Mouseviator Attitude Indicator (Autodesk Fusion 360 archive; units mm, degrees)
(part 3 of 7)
sketch "Sketch4" plane through (0, 2, 0) normal (0, -1, 0) x axis (1, 0, 0)
  line L1 (16.25, 38.3052) -> (16.25, 41.4655)
  line L2 (-16.25, -38.3052) -> (-16.25, -41.2776)
  line L3 (-16.25, -38.3052) -> (-16.25, -41.2776)
  line L4 (38.3052, -16.25) -> (41.2776, -16.25)
  line L5 (16.25, -41.2776) -> (16.25, -38.3052)
  line L6 (16.25, 41.4655) -> (24.1231, 41.4655)
  line L7 (41.2776, 16.25) -> (38.3052, 16.25)
  line L8 (41.2776, 29.1716) -> (41.2776, 16.25)
  line L9 (30.5858, 40.6918) -> (40.6918, 30.5858)
  line L10 (25.492, 41.2776) -> (29.1716, 41.2776)
  line L11 (41.2776, -16.25) -> (41.2776, -29.1716)
  line L12 (-41.2776, -29.1716) -> (-41.2776, -16.25)
  line L13 (-41.2776, -29.1716) -> (-41.2776, -16.25)
  line L14 (-41.2776, -16.25) -> (-38.3052, -16.25)
  line L15 (-30.5858, -40.6918) -> (-40.6918, -30.5858)
  line L16 (-16.25, -41.2776) -> (-29.1716, -41.2776)
  line L17 (29.1716, -41.2776) -> (16.25, -41.2776)
  line L18 (40.6918, -30.5858) -> (30.5858, -40.6918)
  line L19 (38.3052, -16.25) -> (41.2776, -16.25)
  line L20 (-41.2776, -16.25) -> (-38.3052, -16.25)
  line L21 (-30.5858, -40.6918) -> (-40.6918, -30.5858)
  line L22 (-16.25, -41.2776) -> (-29.1716, -41.2776)
  line L23 (16.25, -41.2776) -> (16.25, -38.3052)
  line L24 (29.1716, -41.2776) -> (16.25, -41.2776)
  line L25 (40.6918, -30.5858) -> (30.5858, -40.6918)
  line L26 (41.2776, -16.25) -> (41.2776, -29.1716)
  arc A1 centre (0, 0) radius 41.6095 clockwise from (-16.25, -38.3052) to (-17.58, -37.7133)
  arc A2 centre (0, 0) radius 41.6095 clockwise from (-16.25, -38.3052) to (-17.58, -37.7133)
  arc A3 centre (0, 0) radius 41.6095 clockwise from (17.58, -37.7133) to (16.25, -38.3052)
  circle C1 centre (-18.76, 36.96) radius 3.75
  circle C2 centre (-36.96, 18.76) radius 3.75
  circle C3 centre (-18.76, -36.96) radius 3.75
  circle C4 centre (18.76, -36.96) radius 3.75
  circle C5 centre (36.96, -18.76) radius 3.75
  circle C6 centre (36.96, 18.76) radius 3.75
  circle C7 centre (18.76, 36.96) radius 3.75
  circle C8 centre (-18.76, -36.96) radius 3.75
  circle C9 centre (-36.96, 18.76) radius 1.4
  circle C10 centre (-18.76, 36.96) radius 1.4
  circle C11 centre (18.76, 36.96) radius 1.4
  circle C12 centre (36.96, 18.76) radius 1.4
  circle C13 centre (36.96, -18.76) radius 1.4
  circle C14 centre (18.76, -36.96) radius 1.4
  circle C15 centre (-18.76, -36.96) radius 1.4
  circle C16 centre (-18.76, -36.96) radius 1.4
  arc A4 centre (0, 0) radius 41.6095 clockwise from (16.25, 38.3052) to (17.58, 37.7133)
  circle C17 centre (-36.96, -18.76) radius 3.75
  arc A5 centre (18.76, 36.96) radius 1.4 clockwise from (17.58, 37.7133) to (20.0646, 36.4522)
  arc A6 centre (0, 0) radius 41.6095 clockwise from (20.0646, 36.4522) to (36.4522, 20.0646)
  arc A7 centre (36.96, 18.76) radius 1.4 clockwise from (36.4522, 20.0646) to (37.7133, 17.58)
  arc A8 centre (0, 0) radius 41.6095 clockwise from (37.7133, 17.58) to (38.3052, 16.25)
  arc A9 centre (39.2776, 29.1716) radius 2 clockwise from (40.6918, 30.5858) to (41.2776, 29.1716)
  arc A10 centre (29.1716, 39.2776) radius 2 clockwise from (29.1716, 41.2776) to (30.5858, 40.6918)
  arc A11 centre (24.1231, 36.3855) radius 5.08 clockwise from (24.1231, 41.4655) to (25.492, 41.2776)
  circle C18 centre (31.4309, 31.4309) radius 2.159
  circle C19 centre (-36.96, -18.76) radius 1.4
  circle C20 centre (-31.4309, -31.4309) radius 2.159
  arc A12 centre (-39.2776, -29.1716) radius 2 clockwise from (-40.6918, -30.5858) to (-41.2776, -29.1716)
  arc A13 centre (-29.1716, -39.2776) radius 2 clockwise from (-29.1716, -41.2776) to (-30.5858, -40.6918)
  arc A14 centre (-18.76, -36.96) radius 1.4 clockwise from (-17.58, -37.7133) to (-20.0646, -36.4522)
  arc A15 centre (0, 0) radius 41.6095 clockwise from (-20.0646, -36.4522) to (-36.4522, -20.0646)
  arc A16 centre (-36.96, -18.76) radius 1.4 clockwise from (-36.4522, -20.0646) to (-37.7133, -17.58)
  arc A17 centre (0, 0) radius 41.6095 clockwise from (-37.7133, -17.58) to (-38.3052, -16.25)
  circle C21 centre (31.4309, -31.4309) radius 2.159
  arc A18 centre (0, 0) radius 41.6095 clockwise from (17.58, -37.7133) to (16.25, -38.3052)
  arc A19 centre (29.1716, -39.2776) radius 2 clockwise from (30.5858, -40.6918) to (29.1716, -41.2776)
  arc A20 centre (39.2776, -29.1716) radius 2 clockwise from (41.2776, -29.1716) to (40.6918, -30.5858)
  arc A21 centre (0, 0) radius 41.6095 clockwise from (38.3052, -16.25) to (37.7133, -17.58)
  arc A22 centre (36.96, -18.76) radius 1.4 clockwise from (37.7133, -17.58) to (36.4522, -20.0646)
  arc A23 centre (0, 0) radius 41.6095 clockwise from (36.4522, -20.0646) to (20.0646, -36.4522)
  arc A24 centre (18.76, -36.96) radius 1.4 clockwise from (20.0646, -36.4522) to (17.58, -37.7133)
  circle C22 centre (-31.4309, -31.4309) radius 2.159
  arc A25 centre (-39.2776, -29.1716) radius 2 clockwise from (-40.6918, -30.5858) to (-41.2776, -29.1716)
  arc A26 centre (-29.1716, -39.2776) radius 2 clockwise from (-29.1716, -41.2776) to (-30.5858, -40.6918)
  arc A27 centre (-18.76, -36.96) radius 1.4 clockwise from (-17.58, -37.7133) to (-20.0646, -36.4522)
  arc A28 centre (0, 0) radius 41.6095 clockwise from (-20.0646, -36.4522) to (-36.4522, -20.0646)
  arc A29 centre (-36.96, -18.76) radius 1.4 clockwise from (-36.4522, -20.0646) to (-37.7133, -17.58)
  arc A30 centre (0, 0) radius 41.6095 clockwise from (-37.7133, -17.58) to (-38.3052, -16.25)
  circle C23 centre (31.4309, -31.4309) radius 2.159
  arc A31 centre (29.1716, -39.2776) radius 2
  arc A32 centre (39.2776, -29.1716) radius 2 clockwise from (41.2776, -29.1716) to (40.6918, -30.5858)
  arc A33 centre (0, 0) radius 41.6095 clockwise from (38.3052, -16.25) to (37.7133, -17.58)
  arc A34 centre (36.96, -18.76) radius 1.4 clockwise from (37.7133, -17.58) to (36.4522, -20.0646)
  arc A35 centre (0, 0) radius 41.6095 clockwise from (36.4522, -20.0646) to (20.0646, -36.4522)
  arc A36 centre (18.76, -36.96) radius 1.4 clockwise from (20.0646, -36.4522) to (17.58, -37.7133)
  arc A37 centre (-36.96, -18.76) radius 1.4 clockwise from (-37.7133, -17.58) to (-36.4522, -20.0646)
  concentric C1 C10
  concentric C2 C9
  concentric C3 C15
  concentric C4 C14
  concentric C5 C13
  concentric C6 C12
  concentric C7 C11
  concentric C8 C16
  equal C3 C8
  equal C2 C3
  equal C1 C2
  equal C1 C7
  equal C6 C7
  equal C5 C6
  equal C4 C5
  equal C3 C17
  concentric C17 C19
  dimension "d321" diameter C5 = 7.5
extrude "Extrude4" add sketch "Sketch4" profile of L1 A1 L2 A2 A3 C9 C10 C11 C12 C13 C14 C1 C2 C15 C3 C4 C5 C6 C7 C16 C8 L3 L4 A4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 against normal blind 5
sketch "Sketch2" plane through (0, 1, 0) normal (0, 1, 0) x axis (-1, 0, 0)
  line L1 (-1.35, -41.3) -> (-1.35, -39.627)
  line L2 (1.35, -41.3) -> (-1.35, -41.3)
  line L3 (1.35, -39.627) -> (1.35, -41.3)
  line L4 (9.5326, -23.75) -> (27.9134, -23.75)
  line L5 (3.7293, -12.6019) -> (9.5326, -23.75)
  line L6 (-3.7293, -12.6019) -> (3.7293, -12.6019)
  line L7 (-9.5326, -23.75) -> (-3.7293, -12.6019)
  line L8 (-27.9134, -23.75) -> (-9.5326, -23.75)
  line L9 (-3.543, 32.597) -> (-3.543, 36.4783)
  line L10 (-2.0322, 27.1385) -> (-3.543, 32.597)
  line L11 (-0.9183, 27.1385) -> (-2.0322, 27.1385)
  line L12 (-0.9183, 36.6385) -> (-0.9183, 27.1385)
  line L13 (0.9183, 27.1385) -> (0.9183, 36.6385)
  line L14 (2.0322, 27.1385) -> (0.9183, 27.1385)
  line L15 (3.543, 32.597) -> (2.0322, 27.1385)
  line L16 (3.543, 36.4783) -> (3.543, 32.597)
  line L17 (-31.75, -23.75) -> (31.75, -23.75)
  line L18 (-40.6918, 30.5858) -> (-30.5858, 40.6918)
  line L19 (-41.2776, -29.1716) -> (-41.2776, 29.1716)
  line L20 (-30.5858, -40.6918) -> (-40.6918, -30.5858)
  line L21 (-1.5, -41.2776) -> (-29.1716, -41.2776)
  line L22 (-1.5, -39.6216) -> (-1.5, -41.2776)
  line L23 (1.5, -41.2776) -> (1.5, -39.6216)
  line L24 (29.1716, -41.2776) -> (1.5, -41.2776)
  line L25 (40.6918, -30.5858) -> (30.5858, -40.6918)
  line L26 (41.2776, 29.1716) -> (41.2776, -29.1716)
  line L27 (30.5858, 40.6918) -> (40.6918, 30.5858)
  line L28 (25.502, 41.2776) -> (29.1716, 41.2776)
  line L29 (-24.1231, 41.4655) -> (24.1331, 41.4655)
  line L30 (-29.1716, 41.2776) -> (-25.492, 41.2776)
  arc A1 centre (0, 0) radius 39.65 clockwise from (-1.35, -39.627) to (1.35, -39.627)
  arc A2 centre (0, 0) radius 36.65 clockwise from (-27.9134, -23.75) to (-3.543, 36.4783)
  arc A3 centre (0, 0) radius 36.65 clockwise from (-0.9183, 36.6385) to (0.9183, 36.6385)
  arc A4 centre (0, 0) radius 36.65 clockwise from (3.543, 36.4783) to (27.9134, -23.75)
  arc A5 centre (-39.2776, 29.1716) radius 2 clockwise from (-41.2776, 29.1716) to (-40.6918, 30.5858)
  arc A6 centre (-39.2776, -29.1716) radius 2 clockwise from (-40.6918, -30.5858) to (-41.2776, -29.1716)
  arc A7 centre (-29.1716, -39.2776) radius 2 clockwise from (-29.1716, -41.2776) to (-30.5858, -40.6918)
  arc A8 centre (0, 0) radius 39.65 clockwise from (-1.5, -39.6216) to (1.5, -39.6216)
  arc A9 centre (29.1716, -39.2776) radius 2 clockwise from (30.5858, -40.6918) to (29.1716, -41.2776)
  arc A10 centre (39.2776, -29.1716) radius 2 clockwise from (41.2776, -29.1716) to (40.6918, -30.5858)
  arc A11 centre (39.2776, 29.1716) radius 2 clockwise from (40.6918, 30.5858) to (41.2776, 29.1716)
  arc A12 centre (29.1716, 39.2776) radius 2 clockwise from (29.1716, 41.2776) to (30.5858, 40.6918)
  arc A13 centre (24.1331, 36.3855) radius 5.08 clockwise from (24.1331, 41.4655) to (25.502, 41.2776)
  arc A14 centre (-24.1231, 36.3855) radius 5.08 clockwise from (-25.492, 41.2776) to (-24.1231, 41.4655)
  arc A15 centre (-29.1716, 39.2776) radius 2 clockwise from (-30.5858, 40.6918) to (-29.1716, 41.2776)
  circle C1 centre (-36.96, 18.76) radius 1.4
  circle C2 centre (-18.76, -36.96) radius 1.4
  circle C3 centre (36.96, -18.76) radius 1.4
  circle C4 centre (18.76, 36.96) radius 1.4
  circle C5 centre (36.96, 18.76) radius 1.4
  circle C6 centre (18.76, -36.96) radius 1.4
  circle C7 centre (-36.96, -18.76) radius 1.4
  circle C8 centre (-18.76, 36.96) radius 1.4
  circle C9 centre (-31.4309, 31.4309) radius 2.159
  circle C10 centre (-31.4309, -31.4309) radius 2.159
  circle C11 centre (31.4309, 31.4309) radius 2.159
  circle C12 centre (31.4309, -31.4309) radius 2.159
  point P23 (31.75, -23.75)
  point P24 (-31.75, -23.75)
  point P12 (-27.9134, -23.75)
  coincident A1 P23
  coincident A1 P24
  parallel L4 L17
  horizontal P12 P24
extrude "Extrude3" add sketch "Sketch2" profile of A1 A2 L9 L10 L11 L12 A3 L13 L14 L15 L16 A4 L17 A8 against normal blind 2.5
work_plane "WorkPlane1" AlongDistance -1.5
sketch "Sketch5" plane through (0, 0, 11.5) normal (0, 0, 1) x axis (1, 0, 0)
  line L1 (0, 5.902) -> (-0.4092, 6.2366)
  line L2 (0, 8.6817) -> (0, 0)
  line L3 (0, 5.902) -> (0.4092, 6.2366)
  circle C1 centre (0, 0) radius 6.25
  point P1 (0, 0)
  point P4 (0, 0)
  point P3 (0, 5.902)
  point P2 (-0.4092, 6.2366)
  point P7 (0.4092, 6.2366)
  point P8 (0, 5.902)
  coincident P1 P4
  vertical L2
  coincident P3 L2
  coincident P2 C1
  symmetric P2 L2 P7
  symmetric P3 L2 P8
extrude "Extrude5" cut sketch "Sketch5" profile of L1 C1 L3 along a picked direction blind -5
circular_pattern "C-Pattern1" countU 30 TotalAngle 360
extrude "Extrude5" cut sketch "Lil Microswitch zero nub" profile of C3 C4 to an object
extrude "Extrude5" cut of existing geometry to an object
sketch "Sketch3" plane through (0, 0, 39.7655) normal (0, 0, 1) x axis (-1, 0, 0)
  line L1 (15.15, 6.4) -> (22.19, 6.4)
  line L2 (15.15, 0.15) -> (15.15, 6.4)
  line L3 (5.6554, 0.15) -> (15.15, 0.15)
  line L4 (-15.15, 0.15) -> (-5.6554, 0.15)
  line L5 (-15.15, 6.4) -> (-15.15, 0.15)
  line L6 (-22.19, 6.4) -> (-15.15, 6.4)
  line L7 (-4.7586, 0.1) -> (-22.19, 0.1)
  line L8 (15.15, 0.1) -> (15.15, 0.15)
  line L9 (-15.15, 0.1) -> (-15.15, 0.15)
  line L10 (15.15, 3.275) -> (-15.15, 3.275)
  line L11 (15.15, 0.1) -> (15.15, 3.275)
  line L12 (-15.15, 0.1) -> (15.15, 0.1)
  line L13 (-15.15, 3.275) -> (-15.15, 0.1)
  line L14 (22.19, 0.1) -> (4.7586, 0.1)
  arc A1 centre (-22.19, 3.3) radius 1.6 clockwise from (-20.5902, 3.275) to (-23.7898, 3.275)
  arc A2 centre (-22.19, 3.25) radius 1.6 clockwise from (-23.7898, 3.275) to (-20.5902, 3.275)
  closed curve K1 centre (2.5644, 3.3)
  closed curve K2 centre (-2.5644, 3.3)
  arc A3 centre (-22.19, 3.25) radius 3.15 clockwise from (-22.19, 0.1) to (-22.19, 6.4)
  arc A4 centre (22.19, 3.25) radius 3.15 clockwise from (22.19, 6.4) to (22.19, 0.1)
  arc A5 centre (22.19, 3.25) radius 1.6 clockwise from (20.5902, 3.275) to (23.7898, 3.275)
  arc A6 centre (22.19, 3.3) radius 1.6 clockwise from (23.7898, 3.275) to (20.5902, 3.275)
  circle C1 centre (22.19, 3.25) radius 1.6
  circle C2 centre (-22.19, 3.25) radius 1.6
  point P8 (15.15, 0.15)
  point P25 (15.15, 0.15)
  point P26 (15.15, 0.1)
  point P14 (-15.15, 0.15)
  point P27 (-15.15, 0.15)
  point P29 (-15.15, 3.275)
  coincident P8 P25
  coincident L7 P26
  perpendicular L7 L8
  coincident P14 P27
  perpendicular L7 L9
  horizontal L10
  vertical L11
  horizontal L12
  vertical L13
  midpoint L5 P29
extrude "Extrude6" cut sketch "Sketch3" profile of A1 A6 C1 C2 to an object
extrude "Extrude7" cut sketch "Sketch3" profile of L2 L3 K1 K2 L4 L5 L7 L8 L9 L10 L11 L12 L13 to an object
chamfer "Chamfer1" distance 1
sketch "Sketch1" plane through (26, 0, 0) normal (1, 0, 0) x axis (0, 1, 0)
  line L1 (25.28, 27) -> (57.28, 27)
  line L2 (25.28, 19) -> (25.28, 27)
  line L3 (17.9124, 19) -> (25.28, 19)
  line L4 (25.28, -19) -> (17.9124, -19)
  line L5 (25.28, -27) -> (25.28, -19)
  line L6 (57.28, -27) -> (25.28, -27)
  line L7 (57.28, 27) -> (57.28, -27)
  circle C1 centre (44.28, 0) radius 5
  arc A1 centre (44.28, 0) radius 32.5 clockwise from (14.7028, 13.47) to (17.9124, 19)
  arc A2 centre (44.28, 0) radius 32.5 clockwise from (14.7028, -13.47) to (14.7028, 13.47)
  circle C2 centre (36.955, 17.5) radius 2
  circle C3 centre (36.955, -17.5) radius 2
  circle C4 centre (30.1171, 16.6312) radius 1.6
  circle C5 centre (30.1171, -16.6312) radius 1.6
  arc A3 centre (44.28, 0) radius 32.5 clockwise from (17.9124, -19) to (14.7028, -13.47)
hole "Hole2" HoleDepth 12 HoleDiameter 3.6 TipAngle 180 CSDiameter 6.3 CSAngle 90
extrude "Extrude7" add sketch "Right Arm" profile of L1 L3 L4 C1 L9 A4 L10 A3 to an object
fillet "Fillet1" radius 1 4 1.5
sketch "Sketch7" plane through (30.62, 0, 0) normal (-1, 0, 0) x axis (0, -1, 0)
  line L1 (-44.28, 3.75) -> (-9.9844, 3.75)
  line L2 (-9.9844, -3.75) -> (-44.28, -3.75)
  line L3 (-39.28, -3.75) -> (-24.28, -3.75)
  line L4 (-39.28, 3.75) -> (-39.28, -3.75)
  line L5 (-24.28, 3.75) -> (-39.28, 3.75)
  line L6 (-24.28, -3.75) -> (-24.28, 3.75)
  line L7 (-49.28, -2.25) -> (-49.28, 2.25)
  arc A1 centre (-44.28, 0) radius 34.5 clockwise from (-9.9844, 3.75) to (-9.9844, -3.75)
  arc A2 centre (-44.28, 0) radius 3.75 clockwise from (-44.28, 3.75) to (-44.28, -3.75)
  point P9 (-39.28, 3.75)
  point P7 (-24.28, -3.75)
  point P10 (-24.28, 3.75)
  horizontal L3
  vertical L4
  horizontal L5
  vertical L6
  coincident L1 P9
  coincident L2 P7
  dimension "d393" distance P9 P10 = 15
  dimension "d394" distance P9 L7 = 10
extrude "Extrude8" add sketch "Sketch7" profile of L1 L2 L3 L4 L5 L6 along normal blind 3
external_derived "Analog Master"
sketch "Attitude Hole Trace" plane through (0, 0, 0) normal (0, 1, 0) x axis (1, 0, 0)
  line L1 (-264.7779, -374.3404) -> (-260.0107, -379.2613)
  line L2 (-257.8455, -377.1638) -> (-262.6127, -372.2429)
  line L3 (-197.0382, -372.2859) -> (-201.9591, -377.0531)
  line L4 (-199.8616, -379.2183) -> (-194.9407, -374.4511)
  line L5 (-259.8999, -309.4241) -> (-264.8209, -314.1913)
  line L6 (-262.7234, -316.3565) -> (-257.8025, -311.5893)
  line L7 (-194.9837, -314.302) -> (-199.7509, -309.3811)
  line L8 (-201.9161, -311.4786) -> (-197.1489, -316.3995)
  arc A1 centre (-263.6953, -373.2916) radius 1.5073 clockwise from (-264.7779, -374.3404) to (-262.6127, -372.2429)
  arc A2 centre (-258.9281, -378.2126) radius 1.5073 clockwise from (-257.8455, -377.1638) to (-260.0107, -379.2613)
  circle C1 centre (-229.8808, -344.3212) radius 40.005
  arc A3 centre (-195.9894, -373.3685) radius 1.5073 clockwise from (-197.0382, -372.2859) to (-194.9407, -374.4511)
  arc A4 centre (-200.9104, -378.1357) radius 1.5073 clockwise from (-199.8616, -379.2183) to (-201.9591, -377.0531)
  arc A5 centre (-258.8512, -310.5067) radius 1.5073 clockwise from (-259.8999, -309.4241) to (-257.8025, -311.5893)
  arc A6 centre (-263.7722, -315.2739) radius 1.5073 clockwise from (-262.7234, -316.3565) to (-264.8209, -314.1913)
  arc A7 centre (-196.0663, -315.3508) radius 1.5073 clockwise from (-194.9837, -314.302) to (-197.1489, -316.3995)
  arc A8 centre (-200.8335, -310.4298) radius 1.5073 clockwise from (-201.9161, -311.4786) to (-199.7509, -309.3811)
chamfer "Chamfer1" distance 8
chamfer "Chamfer2" distance 6 distance 8
decal "Decal1"
sketch "Sketch7" plane through (0, 57.28, 0) normal (0, -1, 0) x axis (1, 0, 0)
  line L1 (-26, -14.5) -> (-23, -14.5)
  line L2 (-26, -27) -> (-26, -14.5)
  line L3 (23, -27) -> (-26, -27)
  line L4 (23, 27) -> (23, -27)
  line L5 (-26, 27) -> (23, 27)
  line L6 (-26, 14.5) -> (-26, 27)
  line L7 (-23, 14.5) -> (-26, 14.5)
  line L8 (-23, -14.5) -> (-23, 14.5)
  line L9 (-1.7896, -1.76) -> (1.7896, -1.76)
  line L10 (1.7896, 1.76) -> (-1.7896, 1.76)
  line L11 (-13.75, 8.75) -> (-21.25, 8.75)
  line L12 (-13.75, -8.75) -> (-13.75, 8.75)
  line L13 (-21.25, -8.75) -> (-13.75, -8.75)
  line L14 (-21.25, 8.75) -> (-21.25, -8.75)
  line L15 (-21.25, 8.75) -> (-13.75, 8.75)
  line L16 (-21.25, -8.75) -> (-21.25, 8.75)
  line L17 (-13.75, -8.75) -> (-21.25, -8.75)
  line L18 (-13.75, 8.75) -> (-13.75, -8.75)
  line L19 (26, -27) -> (26, 27)
  line L20 (-26, -27) -> (26, -27)
  line L21 (-26, 27) -> (-26, -27)
  line L22 (-17.1756, 27) -> (-26, 27)
  line L23 (-18.009, 31.2447) -> (-2.1571, 29.8579)
  line L24 (-19.3529, 15.8845) -> (-18.009, 31.2447)
  line L25 (-3.5009, 14.4976) -> (-19.3529, 15.8845)
  line L26 (-2.1571, 29.8579) -> (-3.5009, 14.4976)
  line L27 (-4, 25) -> (-13.4638, 25.828)
  line L28 (26, 27) -> (17.1756, 27)
  line L29 (-2.75, 27.25) -> (-2.75, 31.8816)
  line L30 (2.75, 27.25) -> (-2.75, 27.25)
  line L31 (2.75, 31.8816) -> (2.75, 27.25)
  circle C1 centre (0, -23) radius 2.75
  circle C2 centre (0, 23) radius 2.75
  arc A1 centre (0, 0) radius 2.51 clockwise from (1.7896, 1.76) to (1.7896, -1.76)
  arc A2 centre (0, 0) radius 2.51 clockwise from (-1.7896, -1.76) to (-1.7896, 1.76)
  circle C3 centre (-13.4638, 25.828) radius 1.2
  circle C4 centre (-4, 25) radius 1.2
  circle C5 centre (0, -23) radius 2.75
  circle C6 centre (0, 23) radius 2.75
  circle C7 centre (0, 0) radius 6.25
  arc A3 centre (0, 0) radius 32 clockwise from (2.75, 31.8816) to (17.1756, 27)
  arc A4 centre (0, 0) radius 32 clockwise from (-17.1756, 27) to (-2.75, 31.8816)
  point P21 (-13.4638, 25.828)
  point P38 (-13.4638, 25.828)
  point P22 (-4, 25)
  point P39 (-4, 25)
  perpendicular L23 L24
  parallel L23 L25
  parallel L24 L26
  coincident P21 P38
  coincident P22 P39
  parallel L25 L27
  dimension "d416" distance L23 L27 = 5
  dimension "d417" distance L24 P38 = 5
work_plane "WorkPlane2" AlongDistance -57
sketch "Sketch5" plane through (0, 7, 0.094) normal (0, 1, 0) x axis (1, 0, 0)
  line L1 (-26.6906, -32.6071) -> (-30.1607, -36.0772)
  line L2 (-27.9608, -27.8668) -> (-26.6906, -32.6071)
  line L3 (-32.701, -26.5967) -> (-27.9608, -27.8668)
  line L4 (-36.1712, -30.0668) -> (-32.701, -26.5967)
  line L5 (-34.901, -34.807) -> (-36.1712, -30.0668)
  line L6 (-30.1607, -36.0772) -> (-34.901, -34.807)
  line L7 (-35.2553, -22.1941) -> (-22.1001, -35.3492)
  line L8 (30.0668, -36.1712) -> (26.5967, -32.701)
  line L9 (34.807, -34.901) -> (30.0668, -36.1712)
  line L10 (36.0772, -30.1607) -> (34.807, -34.901)
  line L11 (32.6071, -26.6906) -> (36.0772, -30.1607)
  line L12 (36.1712, 30.0668) -> (32.701, 26.5967)
  line L13 (34.901, 34.807) -> (36.1712, 30.0668)
  line L14 (30.1607, 36.0772) -> (34.901, 34.807)
  line L15 (26.6906, 32.6071) -> (30.1607, 36.0772)
  line L16 (-30.0668, 36.1712) -> (-26.5967, 32.701)
  line L17 (-34.807, 34.901) -> (-30.0668, 36.1712)
  line L18 (-36.0772, 30.1607) -> (-34.807, 34.901)
  line L19 (-32.6071, 26.6906) -> (-36.0772, 30.1607)
  line L20 (-25.7665, -31.6829) -> (-26.6906, -32.6071)
  line L21 (-31.7769, -25.6725) -> (-32.701, -26.5967)
  line L22 (25.6725, -31.7769) -> (26.5967, -32.701)
  line L23 (31.6829, -25.7665) -> (32.6071, -26.6906)
  line L24 (22.1941, -35.2553) -> (35.3492, -22.1001)
  line L25 (31.7769, 25.6725) -> (32.701, 26.5967)
  line L26 (25.7665, 31.6829) -> (26.6906, 32.6071)
  line L27 (35.2553, 22.1941) -> (22.1001, 35.3492)
  line L28 (-25.6725, 31.7769) -> (-26.5967, 32.701)
  line L29 (-31.6829, 25.7665) -> (-32.6071, 26.6906)
  line L30 (-22.1941, 35.2553) -> (-35.3492, 22.1001)
  circle C1 centre (31.4309, -31.3369) radius 2.159
  circle C2 centre (-31.4309, 31.5249) radius 2.159
  circle C3 centre (31.4309, 31.5249) radius 2.159
  circle C4 centre (-31.4309, -31.3369) radius 2.159
  arc A1 centre (0, 0.094) radius 41.6095 clockwise from (-22.1001, -35.1613) to (-35.2553, -22.0062)
  point P11 (-31.4309, -31.3369)
  point P43 (-31.4309, -31.3369)
  point P29 (-25.7665, -31.6829)
  point P30 (-31.7769, -25.6725)
  coincident P11 P43
  perpendicular L1 L7
  coincident L7 P29
  perpendicular L7 L20
  coincident L7 P30
  perpendicular L7 L21
  dimension "d404" distance P11 L6 = 4.25
  dimension "d408" C-Pattern1-Angle = 360
extrude "Extrude6" cut sketch "Sketch5" profile of C1 C4 C2 C3 L1 L2 L3 L4 L5 L6 L8 L9 L10 L11 L12 L13 L14 L15 L16 L17 L18 L19 along normal blind 4
component_insert "Component Insert7"
joint "Assemble9" alignAngle 0 alignOffsetX 0 alignOffsetY 0 alignOffsetZ 1
sketch "Sketch8" plane through (-34.12, 0, 0) normal (-1, 0, 0) x axis (0, -1, 0)
  line L1 (-7.28, -4) -> (-47.78, -4)
  line L2 (-7.28, 4) -> (-7.28, -4)
  line L3 (-47.78, 4) -> (-7.28, 4)
  line L4 (-49.28, -2.5) -> (-49.28, 2.5)
  line L5 (-24.905, -2.625) -> (-19.655, -2.625)
  line L6 (-24.905, 2.625) -> (-24.905, -2.625)
  line L7 (-19.655, 2.625) -> (-24.905, 2.625)
  line L8 (-19.655, -2.625) -> (-19.655, 2.625)
  line L9 (-24.905, 2.625) -> (-19.655, -2.625)
  line L10 (-19.655, 2.625) -> (-24.905, -2.625)
  line L11 (-26.405, 4.125) -> (-18.155, 4.125)
  line L12 (-26.405, -4.125) -> (-26.405, 4.125)
  line L13 (-18.155, -4.125) -> (-26.405, -4.125)
  line L14 (-18.155, 4.125) -> (-18.155, -4.125)
  line L15 (-26.405, -4.125) -> (-18.155, 4.125)
  line L16 (-18.155, -4.125) -> (-26.405, 4.125)
  arc A1 centre (-47.78, -2.5) radius 1.5 clockwise from (-47.78, -4) to (-49.28, -2.5)
  arc A2 centre (-47.78, 2.5) radius 1.5 clockwise from (-49.28, 2.5) to (-47.78, 4)
  circle C1 centre (-44.28, 0) radius 1.5
  point P15 (-22.28, 0)
  point P1 (0, 0)
  point P20 (-22.28, 0)
  point P13 (-24.905, 2.625)
  point P14 (-19.655, 2.625)
  point P12 (-24.905, -2.625)
  point P10 (-44.28, 0)
  horizontal L5
  perpendicular L5 L6
  parallel L5 L7
  parallel L6 L8
  coincident L9 P15
  coincident L10 P15
  horizontal P1 P15
  horizontal L11
  perpendicular L11 L12
  parallel L11 L13
  parallel L12 L14
  coincident L15 P20
  coincident L16 P20
  coincident P15 P20
  dimension "d452" distance P13 P14 = 5.25
  dimension "d453" distance P12 P13 = 5.25
  dimension "d454" distance P10 P15 = 22 (= "MagPitchDim")
  dimension "d456" distance L8 L14 = 1.5
  dimension "d457" distance L7 L11 = 1.5
extrude "Extrude9" add sketch "Sketch8" profile of L1 L3 L5 L6 L7 L8 L12 L14 along normal blind 2.5
extrude "Extrude10" cut of existing geometry blind -2.5
extrude "Extrude11" sketch "Sketch8" profile of L1 L3 L5 L6 L7 L8 L12 L14 blind 1
hole "Hole1" HoleDepth 1 HoleDiameter 2 TipAngle 180
decal "Decal1"
base_feature "Base Feature"
joint "Assemble8" alignAngle -15 alignOffsetX 0 alignOffsetY 0 alignOffsetZ 0
step "C-Pattern" TotalAngle 360
extrude "Extrude12" add sketch "Sketch7" profile of L5 C3 L22 L23 L24 L26 to an object
hole "Hole3" HoleDepth 7 HoleDiameter 2 TipAngle 180 CSDiameter 3 CSAngle 90
sketch "Pitch Hall'" plane through (-23, 0, 0) normal (1, 0, 0) x axis (0, 1, 0)
  line L1 (55.28, -14.5) -> (15.1939, -14.5)
  line L2 (15.1939, 14.5) -> (55.28, 14.5)
  line L3 (19.28, -2.35) -> (25.28, -2.35)
  line L4 (19.28, 2.35) -> (19.28, -2.35)
  line L5 (25.28, 2.35) -> (19.28, 2.35)
  line L6 (25.28, -2.35) -> (25.28, 2.35)
  line L7 (19.28, 2.35) -> (25.28, -2.35)
  line L8 (25.28, 2.35) -> (19.28, -2.35)
  line L9 (25.28, 4.35) -> (17.28, 4.35)
  line L10 (25.28, -4.35) -> (25.28, 4.35)
  line L11 (17.28, -4.35) -> (25.28, -4.35)
  line L12 (17.28, 4.35) -> (17.28, -4.35)
  line L13 (55.28, 14.5) -> (55.28, -14.5)
  circle C1 centre (44.28, 0) radius 1.5
  arc A1 centre (44.28, 0) radius 32.5 clockwise from (15.1939, -14.5) to (15.1939, 14.5)
  point P11 (22.28, 0)
  point P2 (44.28, 0)
  point P10 (25.28, 2.35)
  point P8 (19.28, -2.35)
  point P9 (19.28, 2.35)
  horizontal L3
  perpendicular L3 L4
  parallel L3 L5
  parallel L4 L6
  coincident L7 P11
  coincident L8 P11
  horizontal P2 P11
  horizontal L9
  vertical L10
  horizontal L11
  vertical L12
  coincident P10 L10
  dimension "d462" distance P8 P9 = 4.7
  dimension "d463" distance P9 P10 = 6
  dimension "d464" distance P2 P11 = 22 (= "MagPitchDim")
  dimension "d465" distance L4 L12 = 2
  dimension "d466" distance L5 L9 = 2
  dimension "d467" distance L3 L11 = 2
extrude "Extrude17" cut sketch "Pitch Hall'" profile of L3 L4 L5 L6 L10 against normal blind 2
extrude "Extrude15" add sketch "Pitch Hall'" profile of L3 L4 L5 L9 L10 L11 L12 along normal blind 0.5
extrude "Extrude16" sketch "Pitch Hall'" profile of L3 L4 L5 L6 L9 L10 L11 L12 blind 1
chamfer "Chamfer3" distance 6 distance 2
sketch "Sketch1" plane through (0, -4.75, 0) normal (0, -1, 0) x axis (1, 0, 0)
  line L1 (-14.9494, 36.7238) -> (-14.134, 33.6806)
  line L2 (-1.5, -41.4655) -> (-1.5, -39.6216)
  line L3 (1.5, -41.4655) -> (-1.5, -41.4655)
  line L4 (1.5, -39.6216) -> (1.5, -41.4655)
  line L5 (14.134, 33.6806) -> (14.9494, 36.7238)
  line L6 (0, 37.4678) -> (14.134, 33.6806)
  line L7 (-14.134, 33.6806) -> (0, 37.4678)
  arc A1 centre (0, 0) radius 39.65 clockwise from (-1.5, -39.6216) to (-14.9494, 36.7238)
  arc A2 centre (0, 0) radius 39.65 clockwise from (14.9494, 36.7238) to (1.5, -39.6216)
  circle C1 centre (0, -29.75) radius 3
extrude "Extrude1" cut sketch "Sketch1" profile of C1 no distance stored
fillet "Fillet2" radius 0.5
extrude "Extrude6" add of existing geometry to an object
sketch "Sketch3" plane through (0, -3.75, 0) normal (0, -1, 0) x axis (1, 0, 0)
  line L1 (1.2, -16.3519) -> (1.2, -12.6019)
  line L2 (4.554, -16.3519) -> (1.2, -16.3519)
  line L3 (6.25, -19.6098) -> (4.554, -16.3519)
  line L4 (6.25, -28.75) -> (6.25, -19.6098)
  line L5 (10, -28.75) -> (6.25, -28.75)
  line L6 (10, -30.75) -> (10, -28.75)
  line L7 (6.25, -30.75) -> (10, -30.75)
  line L8 (-6.25, -30.75) -> (-6.25, -36.1132)
  line L9 (-10, -30.75) -> (-6.25, -30.75)
  line L10 (-10, -28.75) -> (-10, -30.75)
  line L11 (-6.25, -28.75) -> (-10, -28.75)
  line L12 (-4.554, -16.3519) -> (-6.25, -19.6098)
  line L13 (-1.2, -12.6019) -> (-1.2, -16.3519)
  line L14 (-3.7293, -12.6019) -> (-1.2, -12.6019)
  line L15 (-9.5326, -23.75) -> (-3.7293, -12.6019)
  line L16 (-27.9134, -23.75) -> (-9.5326, -23.75)
  line L17 (-14.9494, 36.7238) -> (-14.1663, 33.8014)
  line L18 (-1.35, -41.3) -> (-1.35, -39.627)
  line L19 (1.35, -41.3) -> (-1.35, -41.3)
  line L20 (1.35, -39.627) -> (1.35, -41.3)
  line L21 (14.1663, 33.8014) -> (14.9494, 36.7238)
  line L22 (9.5326, -23.75) -> (27.9134, -23.75)
  line L23 (3.7293, -12.6019) -> (9.5326, -23.75)
  line L24 (1.2, -12.6019) -> (3.7293, -12.6019)
  line L25 (-6.25, -46.3) -> (-6.25, -36.1132)
  line L26 (6.25, -46.3) -> (-6.25, -46.3)
  line L27 (6.25, -36.1132) -> (6.25, -46.3)
  line L28 (6.25, -36.1132) -> (6.25, -30.75)
  line L29 (-6.25, -19.6098) -> (-6.25, -28.75)
  line L30 (-1.2, -16.3519) -> (-4.554, -16.3519)
  arc A1 centre (0, 0) radius 36.65 clockwise from (6.25, -36.1132) to (-6.25, -36.1132)
  arc A2 centre (0, 0) radius 36.65 clockwise from (-27.9134, -23.75) to (-14.1663, 33.8014)
  arc A3 centre (0, 0) radius 39.65 clockwise from (-1.35, -39.627) to (-14.9494, 36.7238)
  arc A4 centre (0, 0) radius 39.65 clockwise from (14.9494, 36.7238) to (1.35, -39.627)
  arc A5 centre (0, 0) radius 36.65 clockwise from (14.1663, 33.8014) to (27.9134, -23.75)
  point P11 (-6.25, -36.1132)
  point P35 (-6.25, -36.1132)
  point P10 (6.25, -36.1132)
  point P38 (6.25, -36.1132)
  coincident P11 P35
  parallel L8 L25
  perpendicular L25 L26
  coincident P10 P38
  vertical L27
  dimension "d483" distance L19 L26 = 5
extrude "Extrude7" cut sketch "Sketch3" profile of A1 A3 L18 L19 L20 A4 L25 L26 L27 to an object
extrude "Extrude9" add of existing geometry blind 1
split_face "SplitFace1"
split_face "SplitFace2"
pipe "Pipe1" SectionSize 2 SectionThickness 0.5
pipe "Pipe2" SectionSize 2 SectionThickness 0.5
sketch "Align Nubs" plane through (0, 4.5, 0) normal (0, 1, 0) x axis (-1, 0, 0)
  line L1 (3.75, 30.425) -> (3.75, 35.675)
  line L2 (-3.75, 30.425) -> (3.75, 30.425)
  line L3 (-3.75, 35.675) -> (-3.75, 30.425)
  line L4 (2.25, 37.175) -> (-2.25, 37.175)
  line L5 (-3.75, -30.425) -> (-3.75, -35.675)
  line L6 (3.75, -30.425) -> (-3.75, -30.425)
  line L7 (3.75, -35.675) -> (3.75, -30.425)
  line L8 (-2.25, -37.175) -> (2.25, -37.175)
  line L9 (37.25, 0) -> (34.25, 0)
  line L10 (-38.25, 1) -> (-34.25, 1)
  line L11 (-38.25, -1) -> (-38.25, 1)
  line L12 (-34.25, -1) -> (-38.25, -1)
  line L13 (-34.25, 1) -> (-34.25, -1)
  line L14 (-38.25, -1) -> (-34.25, 1)
  line L15 (-34.25, -1) -> (-38.25, 1)
  line L16 (38.25, 1) -> (34.25, 1)
  line L17 (38.25, -1) -> (38.25, 1)
  line L18 (34.25, -1) -> (38.25, -1)
  line L19 (34.25, 1) -> (34.25, -1)
  line L20 (38.25, -1) -> (34.25, 1)
  line L21 (34.25, -1) -> (38.25, 1)
  circle C1 centre (0, 0) radius 37.25
  arc A1 centre (2.25, 35.675) radius 1.5 clockwise from (2.25, 37.175) to (3.75, 35.675)
  arc A2 centre (-2.25, 35.675) radius 1.5 clockwise from (-3.75, 35.675) to (-2.25, 37.175)
  circle C2 centre (0, 0) radius 27.6721
  arc A3 centre (-2.25, -35.675) radius 1.5 clockwise from (-2.25, -37.175) to (-3.75, -35.675)
  arc A4 centre (2.25, -35.675) radius 1.5 clockwise from (3.75, -35.675) to (2.25, -37.175)
  point P21 (37.25, 0)
  point P19 (0, 0)
  point P20 (34.25, 0)
  point P26 (-36.25, 0)
  point P31 (36.25, 0)
  point P32 (-37.25, 0)
  point P23 (-38.25, 1)
  point P24 (-38.25, -1)
  point P29 (38.25, -1)
  point P30 (34.25, -1)
  point P28 (38.25, 1)
  point P22 (-34.25, 1)
  horizontal L9
  coincident C1 P21
  horizontal P19 P20
  horizontal L10
  perpendicular L10 L11
  parallel L10 L12
  parallel L11 L13
  coincident L14 P26
  coincident L15 P26
  horizontal L16
  perpendicular L16 L17
  parallel L16 L18
  parallel L17 L19
  coincident L20 P31
  coincident L21 P31
  horizontal P19 P26
  coincident C1 P32
  coincident P20 L19
  horizontal P19 P31
  dimension "d520" distance P20 P21 = 3 (= "d519")
  dimension "d521" distance P23 P24 = 2
  dimension "d522" distance P29 P30 = 4
  dimension "d523" distance P28 P29 = 2
  dimension "d526" distance P22 P23 = 4
  dimension "d527" distance L13 P32 = 3
extrude "Extrude6" cut sketch "Align Nubs" profile of C1 L10 L11 L12 L13 L16 L17 L18 L19 against normal blind 0.75 taper -45
sketch "Sketch9" plane through (0, 57.28, 0) normal (0, 1, 0) x axis (-1, 0, 0)
  line L1 (-4.75, 31.6455) -> (-4.75, 35.75)
  line L2 (-26, 27) -> (-17.1756, 27)
  line L3 (-26, -27) -> (-26, 27)
  line L4 (26, -27) -> (-26, -27)
  line L5 (26, 27) -> (26, -27)
  line L6 (17.1756, 27) -> (26, 27)
  line L7 (4.75, 35.75) -> (4.75, 31.6455)
  line L8 (-3.75, 36.75) -> (3.75, 36.75)
  line L9 (21.5, 9) -> (13.5, 9)
  line L10 (21.5, -9) -> (21.5, 9)
  line L11 (13.5, -9) -> (21.5, -9)
  line L12 (13.5, 9) -> (13.5, -9)
  line L13 (-2.75, 29.25) -> (2.75, 29.25)
  line L14 (-2.75, 34.75) -> (-2.75, 29.25)
  line L15 (2.75, 34.75) -> (-2.75, 34.75)
  line L16 (2.75, 29.25) -> (2.75, 34.75)
  curve K1
  curve K2
  curve K3
  curve K4
  arc A1 centre (-3.75, 35.75) radius 1 clockwise from (-4.75, 35.75) to (-3.75, 36.75)
  arc A2 centre (0, 0) radius 32 clockwise from (-17.1756, 27) to (-4.75, 31.6455)
  arc A3 centre (0, 0) radius 32 clockwise from (4.75, 31.6455) to (17.1756, 27)
  arc A4 centre (3.75, 35.75) radius 1 clockwise from (3.75, 36.75) to (4.75, 35.75)
  circle C1 centre (0, -24) radius 2.75
  circle C2 centre (0, 24) radius 2.75
  circle C3 centre (0, 0) radius 6.25
  horizontal K3
  dimension "d529" Text1-Height = 5
extrude "Extrude18" cut sketch "Sketch9" against normal blind 0.5
work_plane "WorkPlane1" AlongDistance 0 named "d28_1_1_1"
work_plane "WorkPlane2" AlongDistance 30 named "d78_1_1_1"
extrude "Extrude1" new body blind 2.5 named "d29_2_1_1"
sketch "Motor Spacers" plane through (0, 39, 0) normal (0, 1, 0) x axis (-1, 0, 0)
  line L1 (36.4994, 34.1766) -> (41.1157, 22.3885)
  line L2 (26.5185, 40.8706) -> (34.1546, 36.8093)
  line L3 (-24.1231, 41.4655) -> (24.1331, 41.4655)
  line L4 (-33.6166, 37.0564) -> (-26.5251, 40.8618)
  line L5 (-41.1157, 22.3885) -> (-36.4994, 34.1766)
  line L6 (-41.4655, -20.5361) -> (-41.4655, 20.5361)
  line L7 (-36.4994, -34.1766) -> (-41.1157, -22.3885)
  line L8 (-23.2139, -41.1177) -> (-33.6166, -37.0564)
  curve K1 (-21.3665, -41.4655) -> (-21.9088, -41.4365)
  line L9 (28.9018, -41.4655) -> (-21.3665, -41.4655)
  line L10 (41.4655, 20.5361) -> (41.4655, -28.9018)
  curve K2 (41.4365, 21.0784) -> (41.4655, 20.5361)
  line L11 (-28.1171, -18.8029) -> (-28.1171, -22.4983)
  line L12 (-21.1171, -22.4983) -> (-21.1171, -18.8029)
  line L13 (-21.1171, 8.8064) -> (-21.1171, 12.5017)
  line L14 (-28.1171, 12.5017) -> (-28.1171, 8.8064)
  line L15 (-2.2528, -17.5616) -> (-4.7199, -20.0288)
  line L16 (-9.6697, -15.0791) -> (-7.2025, -12.6119)
  line L17 (12.6119, 7.2025) -> (15.0791, 9.6697)
  line L18 (20.0288, 4.7199) -> (17.5616, 2.2528)
  line L19 (19.7207, 20.825) -> (23.4161, 20.825)
  line L20 (23.4161, 27.825) -> (19.7207, 27.825)
  line L21 (-7.8886, 27.825) -> (-11.5839, 27.825)
  line L22 (-11.5839, 20.825) -> (-7.8886, 20.825)
  circle C1 centre (36.96, 18.76) radius 1
  circle C2 centre (18.76, 36.96) radius 1
  circle C3 centre (-36.96, -18.76) radius 1
  circle C4 centre (-31.4309, -31.4309) radius 2.159
  circle C5 centre (31.4309, 31.4309) radius 2.159
  arc A1 centre (36.3855, 20.5361) radius 5.08 clockwise from (41.1157, 22.3885) to (41.4365, 21.0784)
  arc A2 centre (31.7692, 32.3242) radius 5.08 clockwise from (34.1546, 36.8093) to (36.4994, 34.1766)
  arc A3 centre (24.1331, 36.3855) radius 5.08 clockwise from (24.1331, 41.4655) to (26.5185, 40.8706)
  arc A4 centre (-24.1231, 36.3855) radius 5.08 clockwise from (-26.5251, 40.8618) to (-24.1231, 41.4655)
  arc A5 centre (-31.7692, 32.3242) radius 5.08 clockwise from (-36.4994, 34.1766) to (-33.6166, 37.0564)
  arc A6 centre (-36.3855, 20.5361) radius 5.08 clockwise from (-41.4655, 20.5361) to (-41.1157, 22.3885)
  arc A7 centre (-36.3855, -20.5361) radius 5.08 clockwise from (-41.1157, -22.3885) to (-41.4655, -20.5361)
  arc A8 centre (-31.7692, -32.3242) radius 5.08 clockwise from (-33.6166, -37.0564) to (-36.4994, -34.1766)
  arc A9 centre (-21.3665, -36.3855) radius 5.08 clockwise from (-21.9088, -41.4365) to (-23.2139, -41.1177)
  arc A10 centre (28.9018, -28.9018) radius 12.5637 clockwise from (41.4655, -28.9018) to (28.9018, -41.4655)
  arc A11 centre (-24.6171, -4.9983) radius 14.2414 clockwise from (-21.1171, -18.8029) to (-28.1171, -18.8029)
  arc A12 centre (-24.6171, -22.4983) radius 3.5 clockwise from (-21.1171, -22.4983) to (-28.1171, -22.4983)
  circle C6 centre (-24.6171, -22.4983) radius 2
  arc A13 centre (-24.6171, -4.9983) radius 14.2414 clockwise from (-28.1171, 8.8064) to (-21.1171, 8.8064)
  arc A14 centre (-24.6171, 12.5017) radius 3.5 clockwise from (-28.1171, 12.5017) to (-21.1171, 12.5017)
  circle C7 centre (-24.6171, 12.5017) radius 2
  arc A15 centre (5.1796, -5.1796) radius 14.4414 clockwise from (-2.2528, -17.5616) to (-7.2025, -12.6119)
  arc A16 centre (-7.1948, -17.5539) radius 3.5 clockwise from (-4.7199, -20.0288) to (-9.6697, -15.0791)
  circle C8 centre (-7.1948, -17.5539) radius 2
  arc A17 centre (5.1796, -5.1796) radius 14.4414 clockwise from (12.6119, 7.2025) to (17.5616, 2.2528)
  arc A18 centre (17.5539, 7.1948) radius 3.5 clockwise from (15.0791, 9.6697) to (20.0288, 4.7199)
  circle C9 centre (17.5539, 7.1948) radius 2
  arc A19 centre (5.9161, 24.325) radius 14.2414 clockwise from (19.7207, 27.825) to (19.7207, 20.825)
  arc A20 centre (23.4161, 24.325) radius 3.5 clockwise from (23.4161, 27.825) to (23.4161, 20.825)
  circle C10 centre (23.4161, 24.325) radius 2
  arc A21 centre (5.9161, 24.325) radius 14.2414 clockwise from (-7.8886, 20.825) to (-7.8886, 27.825)
  arc A22 centre (-11.5839, 24.325) radius 3.5 clockwise from (-11.5839, 20.825) to (-11.5839, 27.825)
  circle C11 centre (-11.5839, 24.325) radius 2
  circle C12 centre (-24.6171, -22.4983) radius 1.4
  circle C13 centre (-24.6171, 12.5017) radius 1.4
  circle C14 centre (-7.1948, -17.5539) radius 1.4
  circle C15 centre (17.5539, 7.1948) radius 1.4
  circle C16 centre (23.4161, 24.325) radius 1.4
  circle C17 centre (-11.5839, 24.325) radius 1.4
  circle C18 centre (-18.76, -36.96) radius 1
  circle C19 centre (0, 0) radius 5
  circle C20 centre (-31.4309, 31.4309) radius 2.159
  circle C21 centre (-36.96, 18.76) radius 1
  circle C22 centre (-18.76, 36.96) radius 1
  circle C23 centre (30.9023, -30.9023) radius 5.5
  point P68 (23.4161, 24.325)
  point P79 (23.4161, 24.325)
  concentric A12 C12
  concentric A14 C13
  concentric A16 C14
  concentric A18 C15
  coincident P68 P79
  concentric A22 C17
  equal C16 C17
  equal C15 C16
  equal C14 C15
  equal C12 C14
  equal C12 C13
  dimension "d76_1_1_1" diameter C13 = 2.8
sketch "Standoffs" plane through (0, 36.5, 0) normal (0, -1, 0) x axis (1, 0, 0)
  curve K1 (-41.4655, 20.5361) -> (-41.4365, 21.0784)
  line L1 (-41.4655, -28.9018) -> (-41.4655, 20.5361)
  line L2 (21.3665, -41.4655) -> (-28.9018, -41.4655)
  curve K2 (21.9088, -41.4365) -> (21.3665, -41.4655)
  line L3 (33.6166, -37.0564) -> (23.2139, -41.1177)
  line L4 (41.1157, -22.3885) -> (36.4994, -34.1766)
  line L5 (41.4655, 20.5361) -> (41.4655, -20.5361)
  line L6 (36.4994, 34.1766) -> (41.1157, 22.3885)
  line L7 (26.5251, 40.8618) -> (33.6166, 37.0564)
  line L8 (-24.1331, 41.4655) -> (24.1231, 41.4655)
  line L9 (-34.1546, 36.8093) -> (-26.5185, 40.8706)
  line L10 (-41.1157, 22.3885) -> (-36.4994, 34.1766)
  arc A1 centre (-36.3855, 20.5361) radius 5.08 clockwise from (-41.4365, 21.0784) to (-41.1157, 22.3885)
  arc A2 centre (-28.9018, -28.9018) radius 12.5637 clockwise from (-28.9018, -41.4655) to (-41.4655, -28.9018)
  arc A3 centre (21.3665, -36.3855) radius 5.08 clockwise from (23.2139, -41.1177) to (21.9088, -41.4365)
  arc A4 centre (31.7692, -32.3242) radius 5.08 clockwise from (36.4994, -34.1766) to (33.6166, -37.0564)
  arc A5 centre (36.3855, -20.5361) radius 5.08 clockwise from (41.4655, -20.5361) to (41.1157, -22.3885)
  arc A6 centre (36.3855, 20.5361) radius 5.08 clockwise from (41.1157, 22.3885) to (41.4655, 20.5361)
  arc A7 centre (31.7692, 32.3242) radius 5.08 clockwise from (33.6166, 37.0564) to (36.4994, 34.1766)
  arc A8 centre (24.1231, 36.3855) radius 5.08 clockwise from (24.1231, 41.4655) to (26.5251, 40.8618)
  arc A9 centre (-24.1331, 36.3855) radius 5.08 clockwise from (-26.5185, 40.8706) to (-24.1331, 41.4655)
  arc A10 centre (-31.7692, 32.3242) radius 5.08 clockwise from (-36.4994, 34.1766) to (-34.1546, 36.8093)
  circle C1 centre (18.76, -36.96) radius 1
  circle C2 centre (-31.4309, 31.4309) radius 2.159
  circle C3 centre (18.76, 36.96) radius 1
  circle C4 centre (-18.76, 36.96) radius 1
  circle C5 centre (31.4309, -31.4309) radius 2.159
  circle C6 centre (31.4309, 31.4309) radius 2.159
  circle C7 centre (-18.76, 36.96) radius 4.0817
  circle C8 centre (18.76, 36.96) radius 3.75
  circle C9 centre (36.96, 18.76) radius 3.75
  circle C10 centre (36.96, -18.76) radius 3.75
  circle C11 centre (18.76, -36.96) radius 3.75
  circle C12 centre (-37.3525, -16.6048) radius 3.75
  circle C13 centre (-17.3319, -36.9825) radius 3.75
  circle C14 centre (-37.3525, -16.6048) radius 1
  circle C15 centre (-17.3319, -36.9825) radius 1
  circle C16 centre (-36.96, 18.76) radius 1
  circle C17 centre (0, 0) radius 5
  circle C18 centre (36.96, -18.76) radius 1
  circle C19 centre (36.96, 18.76) radius 1
  circle C20 centre (-36.96, 18.76) radius 3.75
  point P42 (36.96, -18.76)
  point P53 (36.96, -18.76)
  point P41 (36.96, 18.76)
  point P54 (36.96, 18.76)
  point P1 (0, 0)
  point P44 (-37.3525, -16.6048)
  point P45 (-17.3319, -36.9825)
  concentric C4 C7
  concentric C3 C8
  concentric C1 C11
  equal C8 C9
  equal C9 C10
  equal C10 C11
  concentric C12 C14
  concentric C13 C15
  equal C14 C15
  equal C1 C14
  equal C11 C12
  coincident P42 P53
  coincident P41 P54
  concentric C16 C20
  equal C13 C20
  dimension "d182_1_1_1" diameter C8 = 7.5
  dimension "d282_1_1_1" distance P1 P44 = 16.6048 (= "18.6048175707 mm - 2 mm")
  dimension "d283_1_1_1" distance P1 P44 = 37.3525
  dimension "d284_1_1_1" distance P1 P45 = 17.3319 (= "19.3319078447 mm - 2 mm")
  dimension "d285_1_1_1" distance P1 P45 = 36.9825
sketch "Back Outline" plane through (0, 39, 0) normal (0, 1, 0) x axis (-1, 0, 0)
  line L1 (-36.4994, -34.1766) -> (-41.1157, -22.3885)
  line L2 (-23.2139, -41.1177) -> (-33.6166, -37.0564)
  curve K1 (-21.3665, -41.4655) -> (-21.9088, -41.4365)
  line L3 (28.9018, -41.4655) -> (-21.3665, -41.4655)
  line L4 (41.4655, 20.5361) -> (41.4655, -28.9018)
  curve K2 (41.4365, 21.0784) -> (41.4655, 20.5361)
  line L5 (36.4994, 34.1766) -> (41.1157, 22.3885)
  line L6 (26.5185, 40.8706) -> (34.1546, 36.8093)
  line L7 (-24.1231, 41.4655) -> (24.1331, 41.4655)
  line L8 (-33.6166, 37.0564) -> (-26.5251, 40.8618)
  line L9 (-41.1157, 22.3885) -> (-36.4994, 34.1766)
  line L10 (0, -31.4655) -> (0, 0)
  line L11 (-3.75, -18.1203) -> (-3.75, -31.4655)
  line L12 (3.75, -31.4655) -> (3.75, -0.2296)
  line L13 (0, 0) -> (30.9023, -30.9023)
  line L14 (-2.6517, -2.6517) -> (28.2507, -33.554)
  line L15 (2.6517, 2.6517) -> (33.554, -28.2507)
  line L16 (30.3606, 27.5008) -> (31.4655, 19.6071)
  line L17 (-20.4401, -31.4655) -> (-27.6044, -29.4666)
  line L18 (-22.8865, 31.4655) -> (-17.677, 31.4655)
  line L19 (-27.8686, 28.7921) -> (-22.8865, 31.4655)
  line L20 (-31.4655, 19.6071) -> (-27.8686, 28.7921)
  line L21 (-31.4655, 18.6813) -> (-31.4655, 19.6071)
  line L22 (30.4699, 22.1494) -> (31.4655, 19.6071)
  line L23 (-20.4401, -31.4655) -> (-25.1073, -29.6434)
  line L24 (28.9018, -31.4655) -> (-20.4401, -31.4655)
  line L25 (31.4655, 19.6071) -> (31.4655, -28.9018)
  line L26 (-41.4655, -20.5361) -> (-41.4655, 20.5361)
  arc A1 centre (-36.3855, -20.5361) radius 5.08 clockwise from (-41.1157, -22.3885) to (-41.4655, -20.5361)
  arc A2 centre (-31.7692, -32.3242) radius 5.08 clockwise from (-33.6166, -37.0564) to (-36.4994, -34.1766)
  arc A3 centre (-21.3665, -36.3855) radius 5.08 clockwise from (-21.9088, -41.4365) to (-23.2139, -41.1177)
  arc A4 centre (28.9018, -28.9018) radius 12.5637 clockwise from (41.4655, -28.9018) to (28.9018, -41.4655)
  arc A5 centre (36.3855, 20.5361) radius 5.08 clockwise from (41.1157, 22.3885) to (41.4365, 21.0784)
  arc A6 centre (31.7692, 32.3242) radius 5.08 clockwise from (34.1546, 36.8093) to (36.4994, 34.1766)
  arc A7 centre (24.1331, 36.3855) radius 5.08 clockwise from (24.1331, 41.4655) to (26.5185, 40.8706)
  arc A8 centre (-24.1231, 36.3855) radius 5.08 clockwise from (-26.5251, 40.8618) to (-24.1231, 41.4655)
  arc A9 centre (-31.7692, 32.3242) radius 5.08 clockwise from (-36.4994, 34.1766) to (-33.6166, 37.0564)
  arc A10 centre (-36.3855, 20.5361) radius 5.08 clockwise from (-41.4655, 20.5361) to (-41.1157, 22.3885)
  circle C1 centre (-18.76, 36.96) radius 1
  circle C2 centre (31.4309, 31.4309) radius 2.159
  circle C3 centre (-31.4309, -31.4309) radius 2.159
  circle C4 centre (-18.76, -36.96) radius 1
  circle C5 centre (18.76, 36.96) radius 1
  circle C6 centre (-31.4309, 31.4309) radius 2.159
  circle C7 centre (-36.96, 18.76) radius 1
  circle C8 centre (36.96, 18.76) radius 1
  circle C9 centre (-36.96, -18.76) radius 1
  circle C10 centre (0, 0) radius 22.5
  circle C11 centre (30.9023, -30.9023) radius 15
  arc A11 centre (5.9161, 24.325) radius 24.65 clockwise from (-18.101, 18.7749) to (-17.677, 31.4655)
  arc A12 centre (-24.6171, -4.9983) radius 24.65 clockwise from (-31.4655, 18.6813) to (-18.101, 18.7749)
  arc A13 centre (5.9161, 24.325) radius 24.65 clockwise from (30.4699, 22.1494) to (-0.6001, 0.5519)
  arc A14 centre (-24.6171, -4.9983) radius 24.65 clockwise from (-0.6001, 0.5519) to (-25.1073, -29.6434)
  arc A15 centre (28.9018, -28.9018) radius 2.5637 clockwise from (31.4655, -28.9018) to (28.9018, -31.4655)
  circle C12 centre (36.96, 18.76) radius 1
  circle C13 centre (37.04, -14.76) radius 1
  point P1 (0, 0)
  point P58 (0, 0)
  point P59 (0, -31.4655)
  point P60 (-3.75, -31.4655)
  point P61 (-3.75, -18.1203)
  point P62 (3.75, -0.2296)
  point P63 (3.75, -31.4655)
  point P64 (0, 0)
  point P66 (0, 0)
  point P65 (30.9023, -30.9023)
  point P71 (30.9023, -30.9023)
  coincident P1 P58
  coincident P59 L24
  perpendicular L10 L24
  coincident P60 L24
  coincident P61 A14
  vertical L11
  coincident P62 A13
  coincident P63 L24
  perpendicular L12 L24
  coincident P1 P64
  coincident P1 P66
  coincident P65 P71
  concentric A4 A15
  tangent L24 A15
  tangent A15 L25
  dimension "d337_1_1_1" distance L10 L11 = 3.75 (= "( 7.5 / 2 ) * 1 mm")
  dimension "d338_1_1_1" distance L10 L12 = 3.75 (= "d337_1_1_1")
  dimension "d339_1_1_1" diameter C10 = 45
  dimension "d340_1_1_1" = -3.75 (= "( -7.5 / 2 ) * 1 mm")
  dimension "d341_1_1_1" = 3.75 (= "( 7.5 / 2 ) * 1 mm")
  dimension "d344_1_1_1" diameter C11 = 30
work_plane "WorkPlane2" AlongDistance 0.75 named "d269_1_1_1"
mirror "Mirror1" mirrorStitchTolerance 0.1 named "d277_1_1_1"
hole "Hole1" HoleDepth 6 named "d389_1_1_1" HoleDiameter 2.8 named "d390_1_1_1" TipAngle 180 named "d391_1_1_1"
delete_face "DeleteFace1"
delete_face "DeleteFace2"
delete_face "DeleteFace3"
delete_face "DeleteFace4"
position "Position5"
